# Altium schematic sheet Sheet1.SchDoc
size A2
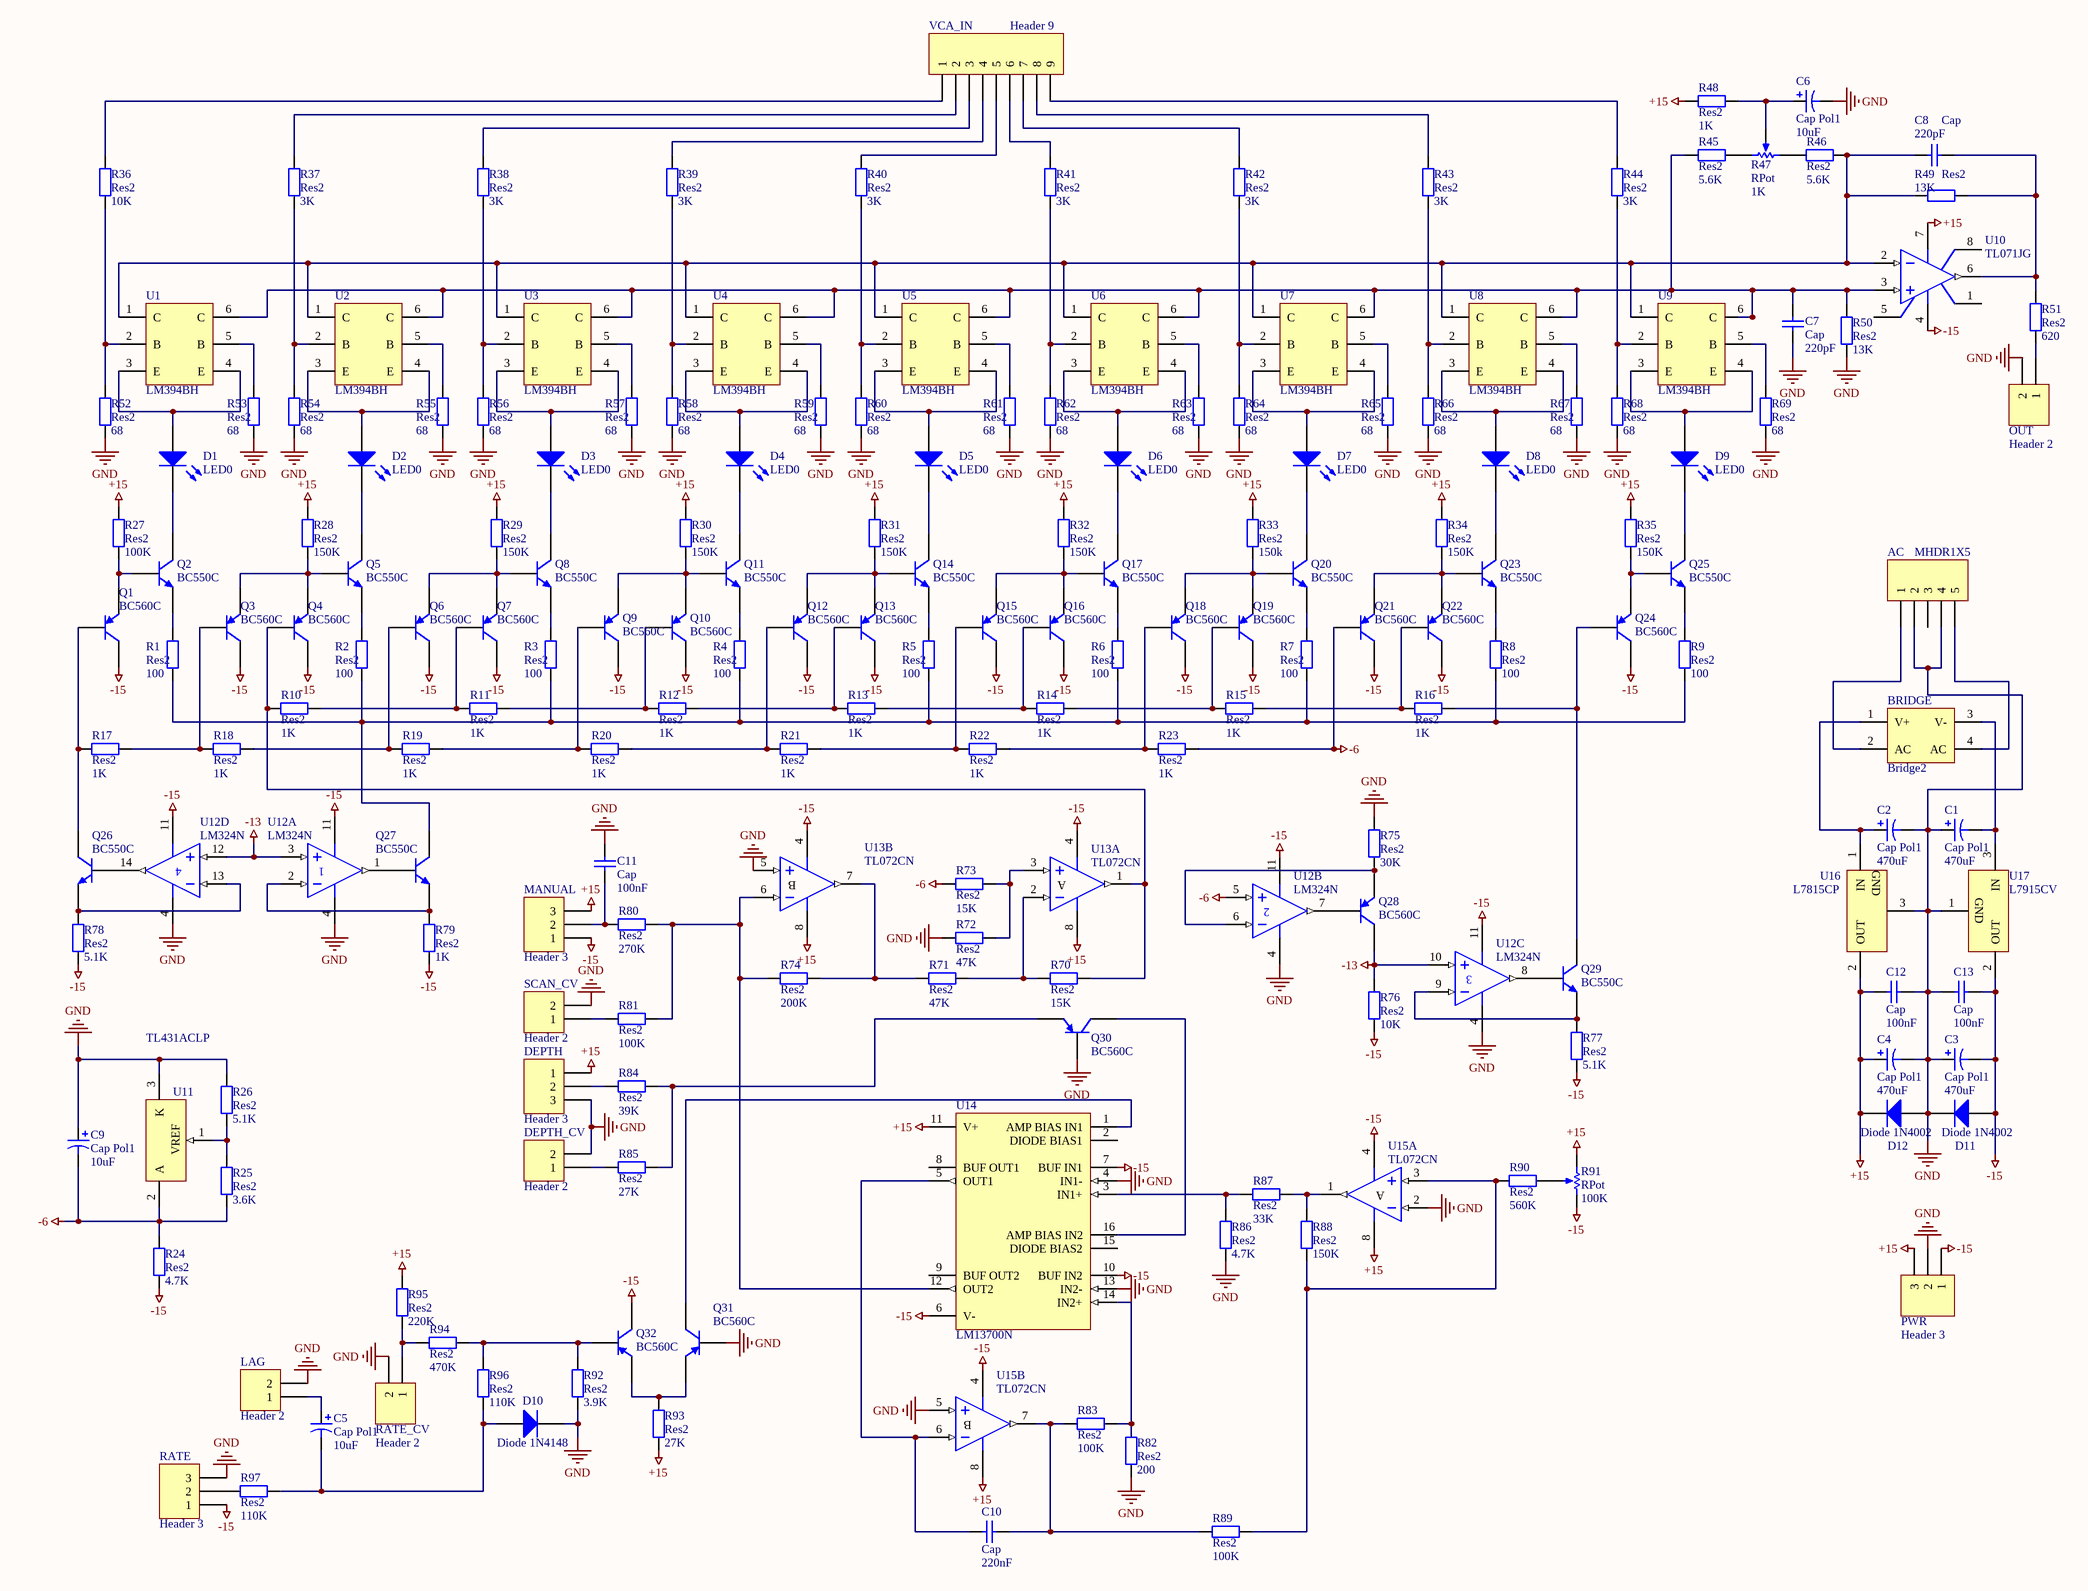
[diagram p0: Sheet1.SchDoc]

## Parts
AC  MHDR1X5  [MHDR1X5]
BRIDGE  Bridge2  [D-46_6A]
C1  Cap Pol1  value 470uF  [B]
C2  Cap Pol1  value 470uF  [B]
C3  Cap Pol1  value 470uF  [B]
C4  Cap Pol1  value 470uF  [B]
C5  Cap Pol1  value 10uF  [B]
C6  Cap Pol1  value 10uF  [B]
C7  Cap  value 220pF  [VP45-3.2]
C8  Cap  value 220pF  [VP45-3.2]
C9  Cap Pol1  value 10uF  [B]
C10  Cap  value 220nF  [VP45-3.2]
C11  Cap  value 100nF  [VP45-3.2]
C12  Cap  value 100nF  [VP45-3.2]
C13  Cap  value 100nF  [VP45-3.2]
D1  LED0  [LED-0]
D2  LED0  [LED-0]
D3  LED0  [LED-0]
D4  LED0  [LED-0]
D5  LED0  [LED-0]
D6  LED0  [LED-0]
D7  LED0  [LED-0]
D8  LED0  [LED-0]
D9  LED0  [LED-0]
D10  Diode 1N4148  [DO-35]
D11  Diode 1N4002  [DO-41]
D12  Diode 1N4002  [DO-41]
DEPTH  Header 3  [HDR1X3]
DEPTH_CV  Header 2  [HDR1X2]
LAG  Header 2  [HDR1X2]
MANUAL  Header 3  [HDR1X3]
OUT  Header 2  [HDR1X2]
PWR  Header 3  [HDR1X3]
Q1  BC560C  [29-04]
Q2  BC550C  [29-04]
Q3  BC560C  [29-04]
Q4  BC560C  [29-04]
Q5  BC550C  [29-04]
Q6  BC560C  [29-04]
Q7  BC560C  [29-04]
Q8  BC550C  [29-04]
Q9  BC560C  [29-04]
Q10  BC560C  [29-04]
Q11  BC550C  [29-04]
Q12  BC560C  [29-04]
Q13  BC560C  [29-04]
Q14  BC550C  [29-04]
Q15  BC560C  [29-04]
Q16  BC560C  [29-04]
Q17  BC550C  [29-04]
Q18  BC560C  [29-04]
Q19  BC560C  [29-04]
Q20  BC550C  [29-04]
Q21  BC560C  [29-04]
Q22  BC560C  [29-04]
Q23  BC550C  [29-04]
Q24  BC560C  [29-04]
Q25  BC550C  [29-04]
Q26  BC550C  [29-04]
Q27  BC550C  [29-04]
Q28  BC560C  [29-04]
Q29  BC550C  [29-04]
Q30  BC560C  [29-04]
Q31  BC560C  [29-04]
Q32  BC560C  [29-04]
R1  Res2  value 100  [AXIAL-0.4]
R2  Res2  value 100  [AXIAL-0.4]
R3  Res2  value 100  [AXIAL-0.4]
R4  Res2  value 100  [AXIAL-0.4]
R5  Res2  value 100  [AXIAL-0.4]
R6  Res2  value 100  [AXIAL-0.4]
R7  Res2  value 100  [AXIAL-0.4]
R8  Res2  value 100  [AXIAL-0.4]
R9  Res2  value 100  [AXIAL-0.4]
R10  Res2  value 1K  [AXIAL-0.4]
R11  Res2  value 1K  [AXIAL-0.4]
R12  Res2  value 1K  [AXIAL-0.4]
R13  Res2  value 1K  [AXIAL-0.4]
R14  Res2  value 1K  [AXIAL-0.4]
R15  Res2  value 1K  [AXIAL-0.4]
R16  Res2  value 1K  [AXIAL-0.4]
R17  Res2  value 1K  [AXIAL-0.4]
R18  Res2  value 1K  [AXIAL-0.4]
R19  Res2  value 1K  [AXIAL-0.4]
R20  Res2  value 1K  [AXIAL-0.4]
R21  Res2  value 1K  [AXIAL-0.4]
R22  Res2  value 1K  [AXIAL-0.4]
R23  Res2  value 1K  [AXIAL-0.4]
R24  Res2  value 4.7K  [AXIAL-0.4]
R25  Res2  value 3.6K  [AXIAL-0.4]
R26  Res2  value 5.1K  [AXIAL-0.4]
R27  Res2  value 100K  [AXIAL-0.4]
R28  Res2  value 150K  [AXIAL-0.4]
R29  Res2  value 150K  [AXIAL-0.4]
R30  Res2  value 150K  [AXIAL-0.4]
R31  Res2  value 150K  [AXIAL-0.4]
R32  Res2  value 150K  [AXIAL-0.4]
R33  Res2  value 150k  [AXIAL-0.4]
R34  Res2  value 150K  [AXIAL-0.4]
R35  Res2  value 150K  [AXIAL-0.4]
R36  Res2  value 10K  [AXIAL-0.4]
R37  Res2  value 3K  [AXIAL-0.4]
R38  Res2  value 3K  [AXIAL-0.4]
R39  Res2  value 3K  [AXIAL-0.4]
R40  Res2  value 3K  [AXIAL-0.4]
R41  Res2  value 3K  [AXIAL-0.4]
R42  Res2  value 3K  [AXIAL-0.4]
R43  Res2  value 3K  [AXIAL-0.4]
R44  Res2  value 3K  [AXIAL-0.4]
R45  Res2  value 5.6K  [AXIAL-0.4]
R46  Res2  value 5.6K  [AXIAL-0.4]
R47  RPot  value 1K  [VR5]
R48  Res2  value 1K  [AXIAL-0.4]
R49  Res2  value 13K  [AXIAL-0.4]
R50  Res2  value 13K  [AXIAL-0.4]
R51  Res2  value 620  [AXIAL-0.4]
R52  Res2  value 68  [AXIAL-0.4]
R53  Res2  value 68  [AXIAL-0.4]
R54  Res2  value 68  [AXIAL-0.4]
R55  Res2  value 68  [AXIAL-0.4]
R56  Res2  value 68  [AXIAL-0.4]
R57  Res2  value 68  [AXIAL-0.4]
R58  Res2  value 68  [AXIAL-0.4]
R59  Res2  value 68  [AXIAL-0.4]
R60  Res2  value 68  [AXIAL-0.4]
R61  Res2  value 68  [AXIAL-0.4]
R62  Res2  value 68  [AXIAL-0.4]
R63  Res2  value 68  [AXIAL-0.4]
R64  Res2  value 68  [AXIAL-0.4]
R65  Res2  value 68  [AXIAL-0.4]
R66  Res2  value 68  [AXIAL-0.4]
R67  Res2  value 68  [AXIAL-0.4]
R68  Res2  value 68  [AXIAL-0.4]
R69  Res2  value 68  [AXIAL-0.4]
R70  Res2  value 15K  [AXIAL-0.4]
R71  Res2  value 47K  [AXIAL-0.4]
R72  Res2  value 47K  [AXIAL-0.4]
R73  Res2  value 15K  [AXIAL-0.4]
R74  Res2  value 200K  [AXIAL-0.4]
R75  Res2  value 30K  [AXIAL-0.4]
R76  Res2  value 10K  [AXIAL-0.4]
R77  Res2  value 5.1K  [AXIAL-0.4]
R78  Res2  value 5.1K  [AXIAL-0.4]
R79  Res2  value 1K  [AXIAL-0.4]
R80  Res2  value 270K  [AXIAL-0.4]
R81  Res2  value 100K  [AXIAL-0.4]
R82  Res2  value 200  [AXIAL-0.4]
R83  Res2  value 100K  [AXIAL-0.4]
R84  Res2  value 39K  [AXIAL-0.4]
R85  Res2  value 27K  [AXIAL-0.4]
R86  Res2  value 4.7K  [AXIAL-0.4]
R87  Res2  value 33K  [AXIAL-0.4]
R88  Res2  value 150K  [AXIAL-0.4]
R89  Res2  value 100K  [AXIAL-0.4]
R90  Res2  value 560K  [AXIAL-0.4]
R91  RPot  value 100K  [VR5]
R92  Res2  value 3.9K  [AXIAL-0.4]
R93  Res2  value 27K  [AXIAL-0.4]
R94  Res2  value 470K  [AXIAL-0.4]
R95  Res2  value 220K  [AXIAL-0.4]
R96  Res2  value 110K  [AXIAL-0.4]
R97  Res2  value 110K  [AXIAL-0.4]
RATE  Header 3  [HDR1X3]
RATE_CV  Header 2  [HDR1X2]
SCAN_CV  Header 2  [HDR1X2]
U1  LM394BH  [H06C]
U2  LM394BH  [H06C]
U3  LM394BH  [H06C]
U4  LM394BH  [H06C]
U5  LM394BH  [H06C]
U6  LM394BH  [H06C]
U7  LM394BH  [H06C]
U8  LM394BH  [H06C]
U9  LM394BH  [H06C]
U10  TL071JG  [JG008]
U11  TL431ACLP  [LP03]
U12  LM324N  [646-06]  (parts A,B,C,D of 4)
U13  TL072CN  [DIP8]  (parts A,B of 2)
U14  LM13700N  [N16E]
U15  TL072CN  [DIP8]  (parts A,B of 2)
U16  L7815CP  [ISOWATT220AB]
U17  L7915CV  [TO220V]
VCA_IN  Header 9  [HDR1X9]

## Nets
+15: C4.1 C12.1 D12.2(K) DEPTH.1 MANUAL.3 PWR.3 R27.2 R28.2 R29.2 R30.2 R31.2 R32.2 R33.2 R34.2 R35.2 R48.2 R91.1(TOP) R93.1 R95.2 U10.7(V+) U13.8(V+) U14.11(V+) U15.8(V+) U16.2(OUT)
-6: C9.2 Q21.2(B) R23.2 R24.2 R25.1 R73.1 U11.2(A) U12.5(IN+)
-13: Q28.1(C) R76.2 U12.3(IN+) U12.10(IN+) U12.12(IN+)
-15: C3.2 C13.2 D11.1(A) MANUAL.1 PWR.1 Q1.1(C) Q3.1(C) Q4.1(C) Q6.1(C) Q7.1(C) Q9.1(C) Q10.1(C) Q12.1(C) Q13.1(C) Q15.1(C) Q16.1(C) Q18.1(C) Q19.1(C) Q21.1(C) Q22.1(C) Q24.1(C) Q32.1(C) R24.1 R76.1 R77.1 R78.1 R79.1 R91.2(BOT) RATE.1 U10.4(V-) U12.11(V-) U13.4(V-) U14.6(V-) U14.7(BUF_IN1) U14.10(BUF_IN2) U15.4(V-) U17.2(OUT)
GND: AC.2 AC.4 C1.1 C2.2 C3.1 C4.2 C6.2 C7.1 C9.1 C11.2 C12.2 C13.1 D10.2(K) D11.2(K) D12.1(A) DEPTH.3 DEPTH_CV.2 LAG.2 OUT.2 PWR.2 Q30.2(B) Q31.2(B) R26.2 R50.1 R52.1 R53.1 R54.1 R55.1 R56.1 R57.1 R58.1 R59.1 R60.1 R61.1 R62.1 R63.1 R64.1 R65.1 R66.1 R67.1 R68.1 R69.1 R72.2 R75.2 R82.1 R86.2 R92.1 RATE.3 RATE_CV.2 SCAN_CV.2 U11.3(K) U12.4(V+) U13.5(IN+) U14.4(IN1-) U14.13(IN2-) U15.2(IN-) U15.5(IN+) U16.3(GND) U17.1(GND)
NetAC_1: AC.1 BRIDGE.2(AC)
NetAC_5: AC.5 BRIDGE.4(AC)
NetBRIDGE_1: BRIDGE.1(V+) C2.1 U16.1(IN)
NetBRIDGE_3: BRIDGE.3(V-) C1.2 U17.3(IN)
NetC5_1: C5.1 LAG.1
NetC5_2: C5.2 D10.1(A) R96.1 R97.2
NetC6_1: C6.1 R47.3(TAP) R48.1
NetC7_2: C7.2 R45.2 R50.2 U1.6(C) U2.6(C) U3.6(C) U4.6(C) U5.6(C) U6.6(C) U7.6(C) U8.6(C) U9.6(C) U10.3(IN+)
NetC8_1: C8.1 R49.1 R51.2 U10.6(OUT)
NetC8_2: C8.2 R46.1 R49.2 U1.1(C) U2.1(C) U3.1(C) U4.1(C) U5.1(C) U6.1(C) U7.1(C) U8.1(C) U9.1(C) U10.2(IN-)
NetC10_1: C10.1 R83.2 R89.2 U15.7(OUT)
NetC10_2: C10.2 U14.5(OUT1) U15.6(IN-)
NetC11_1: C11.1 MANUAL.2 R80.1
NetD1_1: D1.1(A) U1.3(E) U1.4(E)
NetD1_2: D1.2(K) Q2.1(C)
NetD2_1: D2.1(A) U2.3(E) U2.4(E)
NetD2_2: D2.2(K) Q5.1(C)
NetD3_1: D3.1(A) U3.3(E) U3.4(E)
NetD3_2: D3.2(K) Q8.1(C)
NetD4_1: D4.1(A) U4.3(E) U4.4(E)
NetD4_2: D4.2(K) Q11.1(C)
NetD5_1: D5.1(A) U5.3(E) U5.4(E)
NetD5_2: D5.2(K) Q14.1(C)
NetD6_1: D6.1(A) U6.3(E) U6.4(E)
NetD6_2: D6.2(K) Q17.1(C)
NetD7_1: D7.1(A) U7.3(E) U7.4(E)
NetD7_2: D7.2(K) Q20.1(C)
NetD8_1: D8.1(A) U8.3(E) U8.4(E)
NetD8_2: D8.2(K) Q23.1(C)
NetD9_1: D9.1(A) U9.3(E) U9.4(E)
NetD9_2: D9.2(K) Q25.1(C)
NetDEPTH_2: DEPTH.2 R84.1
NetDEPTH_CV_1: DEPTH_CV.1 R85.1
NetOUT_1: OUT.1 R51.1
NetQ1_2: Q1.2(B) Q26.1(C) R17.1
NetQ1_3: Q1.3(E) Q2.2(B) R27.1
NetQ2_3: Q2.3(E) R1.2
NetQ3_2: Q3.2(B) R17.2 R18.1
NetQ3_3: Q3.3(E) Q4.3(E) Q5.2(B) R28.1
NetQ4_2: Q4.2(B) R10.1 R70.2 U13.1(OUT)
NetQ5_3: Q5.3(E) R2.2
NetQ6_2: Q6.2(B) R18.2 R19.1
NetQ6_3: Q6.3(E) Q7.3(E) Q8.2(B) R29.1
NetQ7_2: Q7.2(B) R10.2 R11.1
NetQ8_3: Q8.3(E) R3.2
NetQ9_2: Q9.2(B) R19.2 R20.1
NetQ9_3: Q9.3(E) Q10.3(E) Q11.2(B) R30.1
NetQ10_2: Q10.2(B) R11.2 R12.1
NetQ11_3: Q11.3(E) R4.2
NetQ12_2: Q12.2(B) R20.2 R21.1
NetQ12_3: Q12.3(E) Q13.3(E) Q14.2(B) R31.1
NetQ13_2: Q13.2(B) R12.2 R13.1
NetQ14_3: Q14.3(E) R5.2
NetQ15_2: Q15.2(B) R21.2 R22.1
NetQ15_3: Q15.3(E) Q16.3(E) Q17.2(B) R32.1
NetQ16_2: Q16.2(B) R13.2 R14.1
NetQ17_3: Q17.3(E) R6.2
NetQ18_2: Q18.2(B) R22.2 R23.1
NetQ18_3: Q18.3(E) Q19.3(E) Q20.2(B) R33.1
NetQ19_2: Q19.2(B) R14.2 R15.1
NetQ20_3: Q20.3(E) R7.2
NetQ21_3: Q21.3(E) Q22.3(E) Q23.2(B) R34.1
NetQ22_2: Q22.2(B) R15.2 R16.1
NetQ23_3: Q23.3(E) R8.2
NetQ24_2: Q24.2(B) Q29.1(C) R16.2
NetQ24_3: Q24.3(E) Q25.2(B) R35.1
NetQ25_3: Q25.3(E) R9.2
NetQ26_2: Q26.2(B) U12.14(OUT)
NetQ26_3: Q26.3(E) R78.2 U12.13(IN-)
NetQ27_1: Q27.1(C) R1.1 R2.1 R3.1 R4.1 R5.1 R6.1 R7.1 R8.1 R9.1
NetQ27_2: Q27.2(B) U12.1(OUT)
NetQ27_3: Q27.3(E) R79.2 U12.2(IN-)
NetQ28_2: Q28.2(B) U12.7(OUT)
NetQ28_3: Q28.3(E) R75.1 U12.6(IN-)
NetQ29_2: Q29.2(B) U12.8(OUT)
NetQ29_3: Q29.3(E) R77.2 U12.9(IN-)
NetQ30_1: Q30.1(C) U14.16(AMP_BIAS_IN2)
NetQ30_3: Q30.3(E) R84.2 R85.2
NetQ31_1: Q31.1(C) U14.1(AMP_BIAS_IN1)
NetQ31_3: Q31.3(E) Q32.3(E) R93.2
NetQ32_2: Q32.2(B) R92.2 R94.2 R96.2
NetR25_2: R25.2 R26.1 U11.1(VREF)
NetR36_1: R36.1 R52.2 U1.2(B)
NetR36_2: R36.2 VCA_IN.1
NetR37_1: R37.1 R54.2 U2.2(B)
NetR37_2: R37.2 VCA_IN.2
NetR38_1: R38.1 R56.2 U3.2(B)
NetR38_2: R38.2 VCA_IN.3
NetR39_1: R39.1 R58.2 U4.2(B)
NetR39_2: R39.2 VCA_IN.4
NetR40_1: R40.1 R60.2 U5.2(B)
NetR40_2: R40.2 VCA_IN.5
NetR41_1: R41.1 R62.2 U6.2(B)
NetR41_2: R41.2 VCA_IN.6
NetR42_1: R42.1 R64.2 U7.2(B)
NetR42_2: R42.2 VCA_IN.7
NetR43_1: R43.1 R66.2 U8.2(B)
NetR43_2: R43.2 VCA_IN.8
NetR44_1: R44.1 R68.2 U9.2(B)
NetR44_2: R44.2 VCA_IN.9
NetR45_1: R45.1 R47.2(BOT)
NetR46_2: R46.2 R47.1(TOP)
NetR53_2: R53.2 U1.5(B)
NetR55_2: R55.2 U2.5(B)
NetR57_2: R57.2 U3.5(B)
NetR59_2: R59.2 U4.5(B)
NetR61_2: R61.2 U5.5(B)
NetR63_2: R63.2 U6.5(B)
NetR65_2: R65.2 U7.5(B)
NetR67_2: R67.2 U8.5(B)
NetR69_2: R69.2 U9.5(B)
NetR70_1: R70.1 R71.2 U13.2(IN-)
NetR71_1: R71.1 R74.2 U13.7(OUT)
NetR72_1: R72.1 R73.2 U13.3(IN+)
NetR74_1: R74.1 R80.2 R81.2 U13.6(IN-) U14.12(OUT2)
NetR81_1: R81.1 SCAN_CV.1
NetR82_2: R82.2 R83.1 U14.14(IN2+)
NetR86_1: R86.1 R87.2 U14.3(IN1+)
NetR87_1: R87.1 R88.2 U15.1(OUT)
NetR88_1: R88.1 R89.1 R90.1 U15.3(IN+)
NetR90_2: R90.2 R91.3(TAP)
NetR94_1: R94.1 R95.1 RATE_CV.1
NetR97_1: R97.1 RATE.2

Not connected (* = marked no-connect by the designer): AC 3; U10 1(OS_TRIM) 5(OS_TRIM) 8(NC); U14 2(DIODE_BIAS1) 8(BUF_OUT1) 9(BUF_OUT2) 15(DIODE_BIAS2)

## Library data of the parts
AC = MHDR1X5: Header, 5-Pin
BRIDGE = Bridge2: Diode Bridge
C1-C6 C9 = Cap Pol1: Polarized Capacitor (Radial)
C7 C8 C10-C13 = Cap: Capacitor
D1-D9 = LED0: Typical INFRARED GaAs LED
D10 = Diode 1N4148: High Conductance Fast Diode
D11 D12 = Diode 1N4002: 1 Amp General Purpose Rectifier
DEPTH MANUAL PWR RATE = Header 3: Header, 3-Pin
DEPTH_CV LAG OUT RATE_CV SCAN_CV = Header 2: Header, 2-Pin
Q1 Q3 Q4 Q6 Q7 Q9 Q10 Q12 Q13 Q15 Q16 Q18 Q19 Q21 Q22 Q24 Q28 Q30-Q32 = BC560C: Low Noise Transistor PNP Silicon
Q2 Q5 Q8 Q11 Q14 Q17 Q20 Q23 Q25-Q27 Q29 = BC548C: Amplifier Transistor NPN Silicon
R1-R46 R48-R90 R92-R97 = Res2: Resistor
R47 R91 = RPot: Potentiometer; Sim Note: Enter the Resistance value and the set point into parameter fields.; Set Position: 0.5
U1-U9 = LM394BH: Supermatch Pair; Manufacturer: National Semiconductor; CompType: Amplifiers; PackageTopMarking: NSZXYTTE# LM394BH; MilaeroCode: 2MC
U10 = TL071JG: Low-Noise JFET-Input Operational Amplifier; Note: Pin 8 is not connected
U11 = TL431ACLP: Adjustable Precision Shunt Regulator
U12 = LM324N: Quad Low-Power Operational Amplifier
U13 U15 = TL072CN: Low-Noise J-FET Dual Operational Amplifier
U14 = LM13700N: Dual Operational Transconductance Amplifier with Linearizing Diodes and Buffers; Manufacturer: National Semiconductor; CompType: Amplifiers; PackageTopMarking: NSUZXYYTT*LM13700N
U16 = L7815CP: Positive Voltage Regulator; Note: Tab is connected to pin 3 (GND).
U17 = L7915CV: Negative Voltage Regulator; Note: Tab is connected to pin 3 (IN).
VCA_IN = Header 9: Header, 9-Pin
